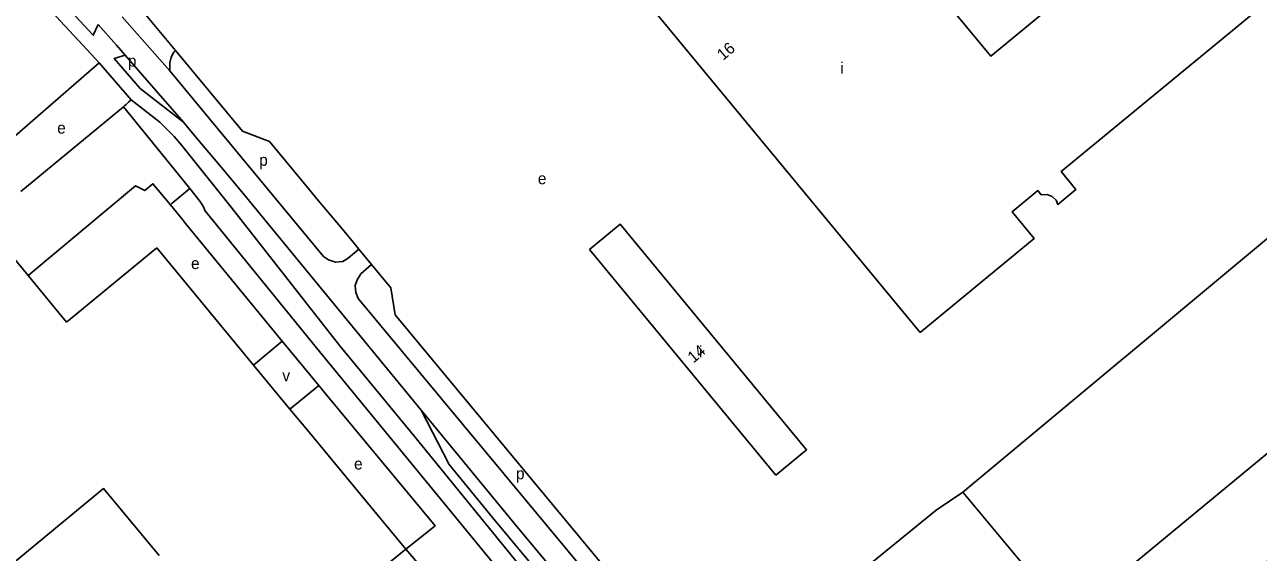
# Model space of a CAD drawing. Extents: x 156097 to 158136, y 385644 to 388348.
# Drawn here: x 157019.8 to 157447.6, y 386978.7 to 387161.9 of the extents above; entities that cross this region are included whole.
import ezdxf

# ---------------------------------------------------------------- set-up
doc = ezdxf.new("R2010")
doc.units = 0
for name, color, linetype in [('BLT_Basislijn', 7, 'Continuous'), ('BLT_Bebouwing', 7, 'Continuous'), ('BLT_Centroide', 7, 'Continuous'), ('BLT_Huisnummer', 7, 'Continuous')]:
    doc.layers.add(name, color=color, linetype=linetype)

msp = doc.modelspace()

# ---------------------------------------------------------------- linework, layer by layer
at = {"layer": 'BLT_Basislijn'}
for p, q in [((157004.35, 387193.14), (157039.88, 387154.84)), ((157053.57, 387164.69), (157070.1, 387145.87)), ((157072.09, 387152.95), (157060.55, 387166.84)), ((157039.88, 387154.84), (157045.55, 387148.73)), ((157006.17, 387114.42), (157045.55, 387148.73)), ((157045.55, 387148.73), (157056.75, 387135.88)), ((157070.1, 387145.87), (157123.42, 387081.4)), ((157068.65, 387115.45), (157054.01, 387133.4)), ((157091.41, 387098.56), (157074.24, 387120.01)), ((157068.65, 387115.45), (157077.03, 387105.03)), ((157080.49, 387100.61), (157077.03, 387105.03)), ((157118.5, 387104.63), (157121.7, 387100.79)), ((157470.72, 387104.42), (157345.15, 386999.62)), ((157097.73, 387100.64), (157157.27, 387028.04)), ((157121.7, 387100.79), (157129.26, 387091.69)), ((157129.1, 387050.39), (157091.41, 387098.56)), ((157075.58, 387092.88), (157109.11, 387052)), ((157129.26, 387091.69), (157132.72, 387087.53)), ((157135.67, 387083.97), (157140.07, 387078.66)), ((157099.12, 387043.76), (157109.11, 387052)), ((157109.11, 387052), (157121.74, 387036.61)), ((157121.74, 387036.61), (157111.73, 387028.47)), ((157124.3, 387033.49), (157121.74, 387036.61)), ((157157.27, 387028.04), (157189.44, 386989.01)), ((157166.96, 387009.16), (157157.27, 387028.04)), ((157182.04, 386990.86), (157166.96, 387009.16)), ((157345.15, 386999.62), (157335.94, 386993.39)), ((157335.94, 386993.39), (157292.12, 386957.75))]:
    msp.add_line(p, q, dxfattribs=at)
for points in [[(157011.56, 387197.53), (157008.29, 387196.25), (157043.55, 387158.24), (157045.22, 387162)], [(157045.22, 387162), (157051.6, 387154.78), (157054.58, 387151.36)], [(157054.58, 387151.36), (157050.82, 387150.16), (157059.85, 387139.81), (157074.79, 387128.04)], [(157054.58, 387151.36), (157060.65, 387144.42), (157074.79, 387128.04)], [(157070.1, 387145.87), (157070.1, 387148.63), (157070.55, 387150.6), (157071.46, 387152.39), (157072.09, 387152.95)], [(157118.5, 387104.63), (157104.66, 387121.31), (157095.3, 387124.99), (157072.09, 387152.95)], [(157018.47, 387103.95), (157054.01, 387133.4)], [(157054.01, 387133.4), (157054.46, 387133.81), (157054.92, 387134.22), (157055.37, 387134.63), (157055.82, 387135.04), (157056.75, 387135.88)], [(157056.75, 387135.88), (157066.69, 387128.05), (157071.63, 387123.07), (157074.24, 387120.01)], [(157074.79, 387128.04), (157078.55, 387123.56), (157087.41, 387113.05), (157096.2, 387102.49), (157097.73, 387100.64)], [(157020.95, 387074.81), (157058.22, 387105.96), (157061.45, 387104.34), (157064.24, 387106.71), (157070.3, 387099.42)], [(157077.03, 387105.03), (157070.97, 387100), (157070.3, 387099.42)], [(157070.3, 387099.42), (157074.46, 387094.24), (157075.58, 387092.88)], [(157081.91, 387098.46), (157080.97, 387100), (157080.49, 387100.61)], [(157188.15, 386884.92), (157226.06, 386915.59), (157228.61, 386918.1), (157228.51, 386918.57), (157120.99, 387049.68), (157082.22, 387097.44), (157081.91, 387098.46)], [(157132.72, 387087.53), (157135.67, 387083.97)], [(157123.42, 387081.4), (157125.1, 387080.24), (157127.56, 387079.5), (157130.14, 387079.75), (157131.97, 387080.89), (157135.67, 387083.97)], [(157140.07, 387078.66), (157136.35, 387075.42), (157135.07, 387073.38), (157134.4, 387071.31), (157134.57, 387068.89), (157135.44, 387066.9)], [(157140.07, 387078.66), (157146.77, 387070.58), (157148.22, 387061.17), (157229.92, 386962.68)], [(157135.44, 387066.9), (157222.47, 386962.04)], [(157241.01, 386913.29), (157155.11, 387018.88), (157129.1, 387050.39)], [(157124.3, 387033.49), (157162.11, 386987.87), (157151.96, 386979.86)], [(157345.15, 386999.62), (157381.52, 386955.83)], [(157244.51, 386915.6), (157182.04, 386990.86)], [(157189.44, 386989.01), (157216.47, 386956.48), (157232.57, 386936.49)], [(157142.74, 386972.25), (157148.27, 386965.6), (157150.27, 386964.96), (157152.82, 386965.66), (157157.18, 386968.87), (157157.54, 386969.83), (157157.44, 386973.44), (157151.96, 386979.86)]]:
    msp.add_lwpolyline(points, dxfattribs=at)
at = {"layer": 'BLT_Bebouwing'}
for p, q in [((157065.55, 387084.48), (157034.27, 387058.68)), ((157151.96, 386979.86), (157142.74, 386972.25))]:
    msp.add_line(p, q, dxfattribs=at)
for points in [[(157330.32, 387055.02), (157369.92, 387087.72), (157362.29, 387096.97), (157371.11, 387104.35), (157372.36, 387102.86), (157374.45, 387102.96), (157376.12, 387102.26), (157377.56, 387100.99), (157378.05, 387099.5), (157384.37, 387104.72), (157379.21, 387110.93), (157469.96, 387185.87), (157477.56, 387176.69), (157497.38, 387193.06), (157460.35, 387237.99), (157354.89, 387150.97), (157319.99, 387193.25), (157413.54, 387270.58), (157422.05, 387261.11), (157441.45, 387277.16), (157403.93, 387322.7), (157252.98, 387198.06), (157197.06, 387265.8), (157172.83, 387245.77)], [(157215.63, 387083.89), (157226.26, 387092.72), (157290.93, 387014.33), (157280.32, 387005.53)]]:
    msp.add_lwpolyline(points, close=True, dxfattribs=at)
for points in [[(157020.95, 387074.81), (156988.71, 387113.85), (156903.22, 387043.24), (156925.76, 387015.95), (156841.4, 386946.35), (156863.25, 386919.87), (156851.23, 386909.97)], [(157099.12, 387043.76), (157065.55, 387084.48)], [(157034.27, 387058.68), (157020.95, 387074.81)], [(157111.73, 387028.47), (157099.12, 387043.76)], [(157381.52, 386955.83), (157483.87, 387040.42), (157502.2, 387018.23), (157399.23, 386933.1), (157417.83, 386910.59), (157445.69, 386933.62), (157454.08, 386923.48), (157587.31, 387033.54), (157640.68, 386968.97), (157445.3, 386807.51)], [(157111.73, 387028.47), (157118.42, 387020.43), (157135.31, 387000), (157151.96, 386979.86)], [(157066.37, 386977.57), (157047.13, 387000.88), (157000.31, 386962.25)]]:
    msp.add_lwpolyline(points, dxfattribs=at)

# ---------------------------------------------------------------- texts
at = {"layer": 'BLT_Centroide'}
for s, p in [('p', (157055.55, 387147.37)), ('i', (157302.63, 387144.91)), ('e', (157031.03, 387124.11)), ('p', (157101.09, 387112.94)), ('e', (157197.75, 387106.53)), ('e', (157077.46, 387077.07)), ('i', (157253.66, 387046.41)), ('v', (157109.12, 387038.1)), ('e', (157134, 387007.49)), ('p', (157190.15, 387004.1))]:
    msp.add_text(s, height=4, dxfattribs=at).set_placement(p)
at = {"layer": 'BLT_Huisnummer'}
for s, p in [('16', (157261.95, 387149.31)), ('14', (157251.72, 387044.26))]:
    msp.add_text(s, height=4, rotation=39.6471, dxfattribs=at).set_placement(p)

doc.saveas('drawing.dxf')
